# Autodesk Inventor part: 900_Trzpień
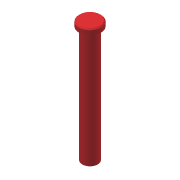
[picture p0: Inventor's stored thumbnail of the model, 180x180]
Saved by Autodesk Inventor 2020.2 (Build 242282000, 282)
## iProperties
Created: 2006-01
Part Number: 900_Trzpień
Document SubType Name: Modeling
Designer: F.Stasiak
Density: 1 g/cm^3
Material: Ogólny
Appearance: Czerwony (jasny)
Manager: www.cadconsulting.pl
Company: Fabian Stasiak CAD Consulting
Author: F.Stasiak
Subject: Zbiór ćwiczeń. Autodesk Inventor 2020. Kurs podstawowy
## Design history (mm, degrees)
sketch "Szkic1"
  geometry: C1 r 7 at (0, 0); 1 further point
  constraints: 1 centre point, 1 coincident
  dimensions: "d0" = 14 diameter of C1
extrude "Wyciągnięcie proste1" new body sketch "Szkic1" distance "d1" = 105; taper "d2" = 0 deg
sketch "Szkic2"
  geometry: C1 r 7 at (0, 0) reference; C2 r 10 at (0, 0)
  constraints: 1 centre point, 1 coincident
  dimensions: "d3" = 20 diameter of C2
extrude "Wyciągnięcie proste2" join sketch "Szkic2" distance "d4" = 5; taper "d5" = 0 deg
chamfer "Faza1" distance "d6" = 1; stored, may be unused: second distance "d7" = 2, angle "d8" = 45 deg
node "Bryła1"
node "Korpusy bryłowe"
node "Korpusy powierzchniowe"
